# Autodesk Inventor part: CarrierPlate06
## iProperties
Created: 2008-02
Part Number: CarrierPlate06
Document SubType Name: Modeling
Designer: grh
Density: 1 g/cm^3
Author: grh
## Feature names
1. Extrusion1
